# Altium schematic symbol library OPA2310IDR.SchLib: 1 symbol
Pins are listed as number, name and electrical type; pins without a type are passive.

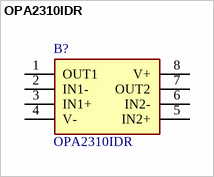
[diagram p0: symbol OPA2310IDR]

## OPA2310IDR
designator B?
General Purpose Amplifier 2 Circuit Rail-to-Rail 8-SOIC; Manufacturer_Name: Texas Instruments; Geometry.Height: 1.75mm
footprint SOIC127P600X175-8N
pins: 1 OUT1, 2 IN1-, 3 IN1+, 4 V-, 5 IN2+, 6 IN2-, 7 OUT2, 8 V+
